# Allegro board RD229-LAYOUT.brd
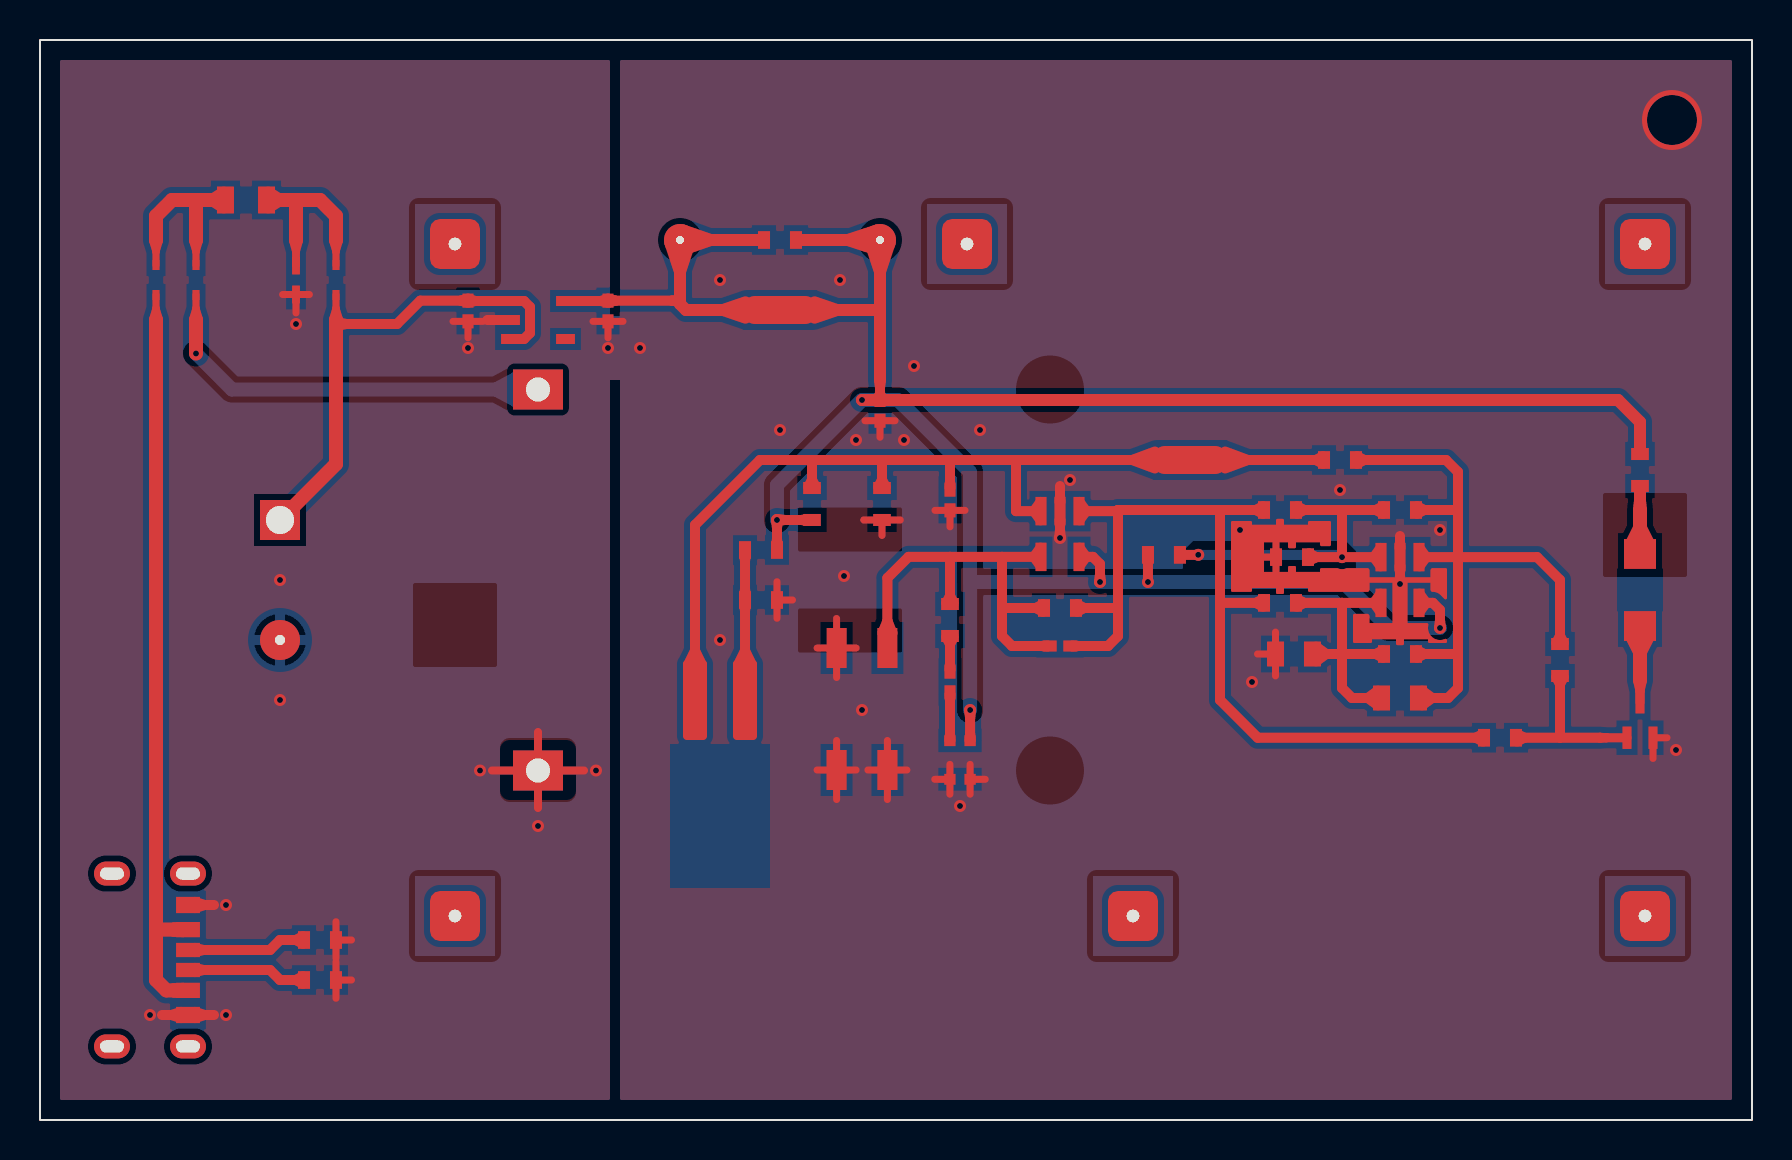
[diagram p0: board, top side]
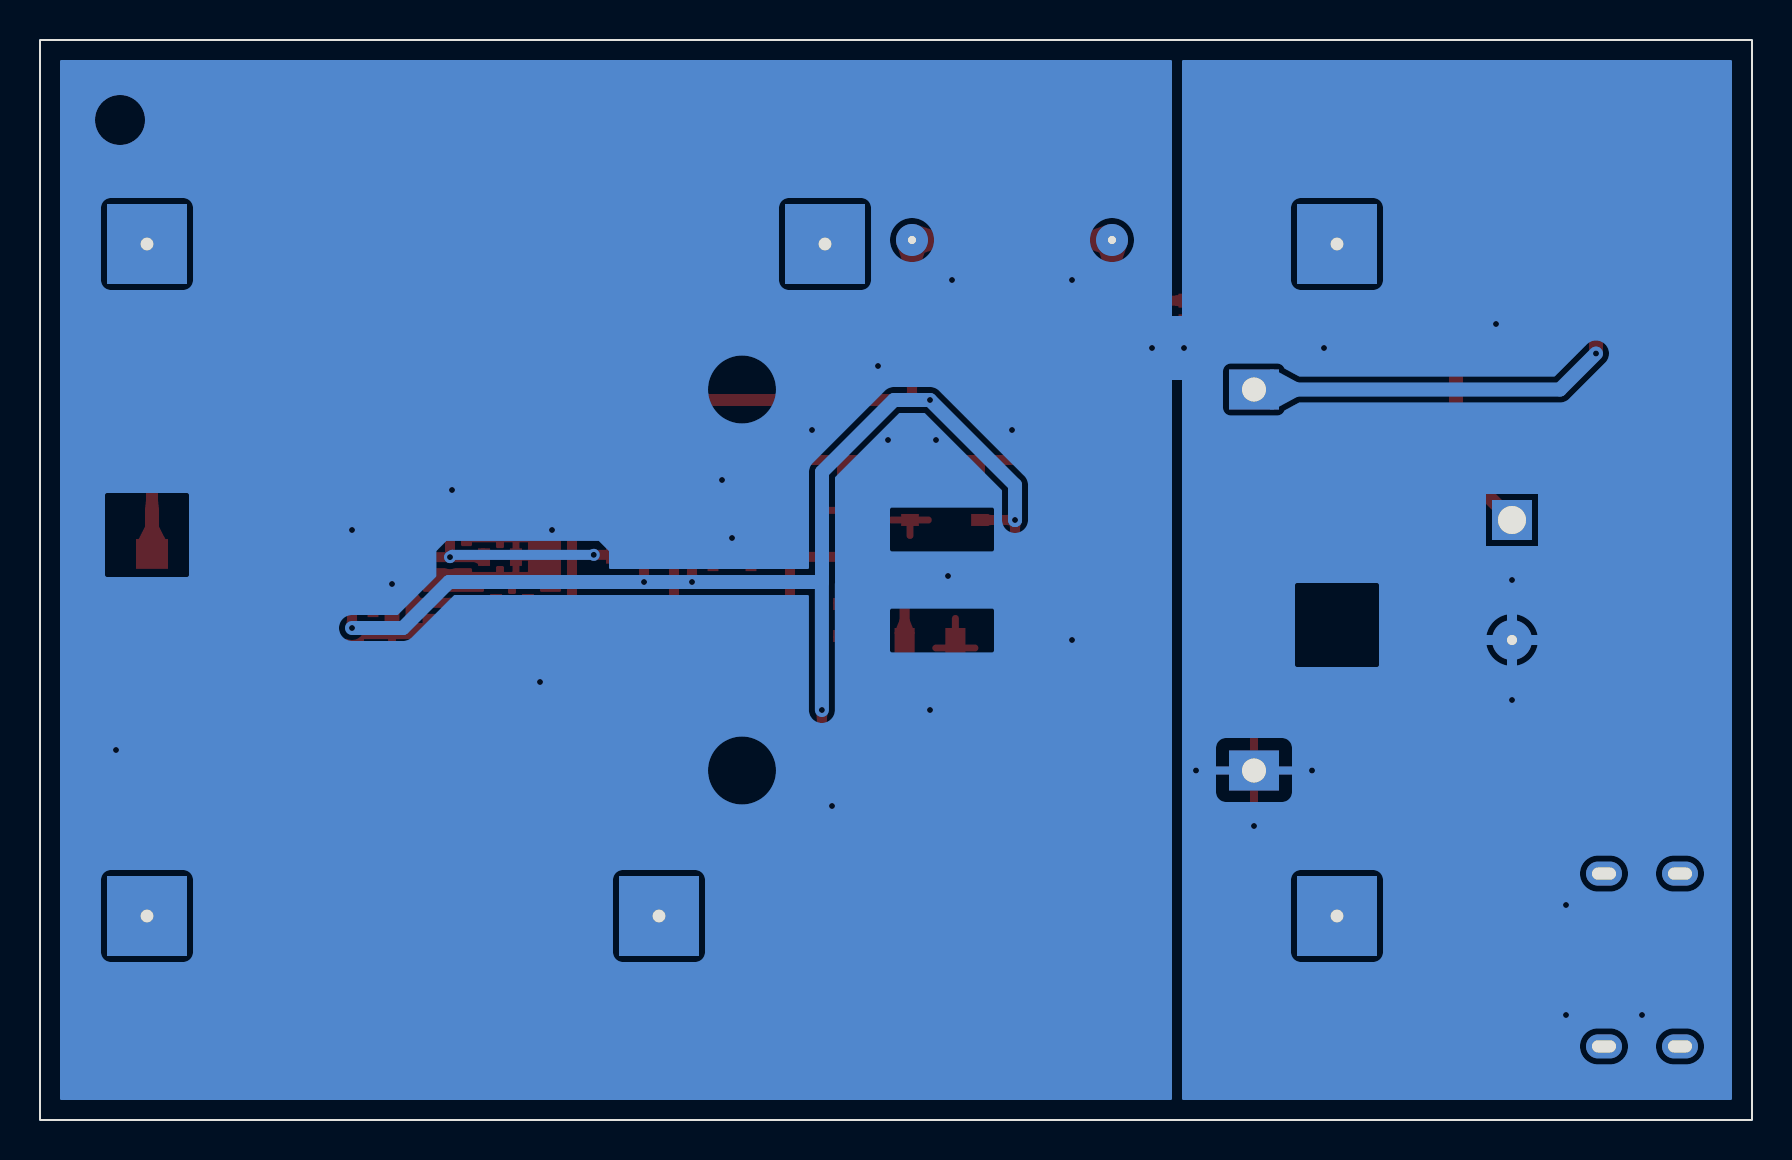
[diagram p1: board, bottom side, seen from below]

Outline 85.6 x 54 mm; copper layers: TOP, BOTTOM. Coordinates in mm from the lower left corner of the outline.
Outline path: rectangle 0,0 85.6,54

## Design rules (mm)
constraint set DEFAULT: 

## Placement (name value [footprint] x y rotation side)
C1  -  [CAP_GRM155B11A10]  21.4 40.45 90 top
C2  -  [CAP_GRM155B11A10]  28.4 40.45 90 top
C3  -  [CAP_GRM155B11A10]  42 35.48 90 top
C4  -  [CAP_GRM155B11A10]  45.5 21.9 270 top
C5  -  [CAP_GRM155B11A10]  45.5 31 90 top
C6  -  [CAP_GRM155B11A10]  51 23.7 0 top
C7  -  [G_21_MUR]  62.7 23.3 0 top
C8  -  [G_21_MUR]  68 21.1 0 top
CN1  -  [CONN6_125_GF_A_0]  5.5 8 270 top
D1  -  [ESC_TOS]  5.8 42 270 top
D2  -  [ESC_TOS]  7.8 42 270 top
D3  -  [SOD523_NEX]  12.8 42 270 top
D4  -  [ESC_TOS]  14.8 42 90 top
EDLC1  -  [CAP_EEC_F5R5U105]  12 27 0 top
JP1  -  [RES_TTD1002F_KOA_2]  37 44 0 top
JP2  -  [RES_TTD1002F_KOA_2]  36.05 28.5 0 top
JP3  -  [RES_TTD1002F_KOA_2]  36.05 26 0 top
JP4  -  [RES_TTD1002F_KOA_2]  73 19.11 0 top
JP5  -  [RES_TTD1002F_KOA_2]  76 23 270 top
LED1  -  [LED_LTST_C230KGK]  80 26.5 90 top
M1  -  [CMM2718AT42308TR]  46 18 0 top
OP1  -  [SOT_25__SMV_T]  51 29.3 270 top
OP2  -  [SOT_25__SMV_T]  68 27 270 top
PD1  -  [PD_4]  41.1 20.5 270 top
Q1  -  [USM_TOS]  80 20 0 top
R1  -  [RES_TTD1002F_KOA_2]  80 32.5 270 top
R2  -  [RES_TTD1002F_KOA_2]  45.5 25 270 top
R3  -  [RES_TTD1002F_KOA_2]  38.6 30.8 270 top
R4  -  [RES_TTD1002F_KOA_2]  42.1 30.8 90 top
R5  -  [RES_TTD1002F_KOA_2]  51 25.6 0 top
R6  -  [RES_TTD1002F_KOA_2]  62 30.5 0 top
R7  -  [RES_TTD1002F_KOA_2]  68 30.5 0 top
R8  -  [RES_TTD1002F_KOA_2]  62.6 28.14 0 top
R9  -  [RES_TTD1002F_KOA_2]  68 23.3 0 top
R10  -  [RES_TTD1002F_KOA_2]  62 25.86 0 top
R11  -  [RES_TTD1002F_KOA_2]  65 33 180 top
R12  -  [RES_TTD1002F_KOA_2]  14 9 180 top
R13  -  [RES_TTD1002F_KOA_2]  14 7 180 top
R14  -  [RES_RK73H2A_KOA]  10.3 46 180 top
R15  -  [RES_TTD1002F_KOA_2]  56.2 28.26 0 top
S1  -  [FSR400_S]  34 21 270 top
SJ1  -  [SJ_1_1]  37 40.5 0 top
SJ2  -  [SJ_1_1]  57.5 33 0 top
SM1  -  [SOLAR_CELL_2]  50.5 27 0 bottom
TP1  -  [T_PAD]  32 44 0 top
TP2  -  [T_PAD]  42 44 0 top
U1  -  [SMV_SOT_25_SC_7]  24.9 40 0 top

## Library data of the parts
C1-C6 = GRM155B11A104KA0: alternate symbols: (T:CAP_GRM155B11A10,CAP_GRM155B11A10_2,CAP_GRM155B11A10_3,CAP_GRM155B11A10_1,CAP_GRM155B11A10_4,CAP_GRM155B11A10_5;B:CAP_GRM155B11A10_B,CAP_GRM155B11A10_2_B,CAP_GRM155B11A10_3_B,CAP_GRM155B11A10_1_B,CAP_GRM155B11A10_4_B,CAP_GRM155B11A10_5_B)
C7 C8 = GRM21BR60J226ME3: alternate symbols: (T:G_21_MUR,G_21_MUR_1;B:G_21_MUR_B,G_21_MUR_1_B)
CN1 = USB4125-GF-A-019: alternate symbols: (T:CONN6_125_GF_A_0;B:CONN6_125_GF_A_0_B)
D1 D2 D4 = 1SS389_L3F_T: alternate symbols: (T:ESC_TOS,ESC_TOS_1,ESC_TOS_2;B:ESC_TOS_B,ESC_TOS_1_B,ESC_TOS_2_B)
D3 = PESD15VS1UB: alternate symbols: (T:SOD523_NEX;B:SOD523_NEX_B)
EDLC1 = EEC-F5R5U105: alternate symbols: (T:CAP_EEC_F5R5U105;B:CAP_EEC_F5R5U105_B)
JP1-JP5 R1-R13 R15 = RK73H1JTTD1002F: alternate symbols: (T:RES_TTD1002F_KOA_2,RES_TTD1002F_KOA_16,RES_TTD1002F_KOA_17,RES_TTD1002F_KOA_3,RES_TTD1002F_KOA_4,RES_TTD1002F_KOA_1,RES_TTD1002F_KOA_13,RES_TTD1002F_KOA,RES_TTD1002F_KOA_14,RES_TTD1002F_KOA_12,RES_TTD1002F_KOA_5,RES_TTD1002F_KOA_6,RES_TTD1002F_KOA_7,RES_TTD1002F_KOA_8,RES_TTD1002F_KOA_9,RES_TTD1002F_KOA_10,RES_TTD1002F_KOA_11,RES_TTD1002F_KOA_15;B:RES_TTD1002F_KOA_2_B,RES_TTD1002F_KOA_16_B,RES_TTD1002F_KOA_17_B,RES_TTD1002F_KOA_3_B,RES_TTD1002F_KOA_4_B,RES_TTD1002F_KOA_1_B,RES_TTD1002F_KOA_13_B,RES_TTD1002F_KOA_B,RES_TTD1002F_KOA_14_B,RES_TTD1002F_KOA_12_B,RES_TTD1002F_KOA_5_B,RES_TTD1002F_KOA_6_B,RES_TTD1002F_KOA_7_B,RES_TTD1002F_KOA_8_B,RES_TTD1002F_KOA_9_B,RES_TTD1002F_KOA_10_B,RES_TTD1002F_KOA_11_B,RES_TTD1002F_KOA_15_B)
LED1 = LTST-C230KGKT: alternate symbols: (T:LED_LTST_C230KGK;B:LED_LTST_C230KGK_B)
M1 = CMM-2718AT-42308-TR: alternate symbols: (T:CMM2718AT42308TR;B:CMM2718AT42308TR_B)
OP1 OP2 = TC75S102F_LF_CT: alternate symbols: (T:SOT_25__SMV_T,SOT_25__SMV_T_2;B:SOT_25__SMV_T_B,SOT_25__SMV_T_2_B)
PD1 = S7184: alternate symbols: (T:PD_4;B:PD_4_B)
Q1 = SSM3K15AFU_LF_T: alternate symbols: (T:USM_TOS;B:USM_TOS_B)
R14 = RK73H2ATTD1003F: alternate symbols: (T:RES_RK73H2A_KOA;B:RES_RK73H2A_KOA_B)
S1 = FSR400-S: alternate symbols: (T:FSR400_S;B:FSR400_S_B)
SJ1 SJ2 = SJ-1: alternate symbols: (T:SJ_1_1;B:SJ_1_1_B)
SM1 = LR0GC02: alternate symbols: (T:solar_cell_2;B:solar_cell_2_B)
TP1 TP2 = T-PAD1: alternate symbols: (T:T_PAD;B:T_PAD_B)
U1 = TCR3UF20A_LM_CT: alternate symbols: (T:SMV_SOT_25_SC_7;B:SMV_SOT_25_SC_7_B)

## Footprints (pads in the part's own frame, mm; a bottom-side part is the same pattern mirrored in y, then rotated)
CAP_EEC_F5R5U105
  rect 2x2 hole 1.4: 1(0,3)
  custom 0.5x0.5 hole 1.4: 2(0,-3)
CAP_GRM155B11A10
  custom 0.138x0.138 smd: 1(-0.518,0) 2(0.518,0)
CMM2718AT42308TR
  custom 0.135x0.135 smd: 1(0.505,0.965) 2(0.505,-0.965) 3(-0.505,-0.965) 4(-0.505,0.965)
CONN6_125_GF_A_0
  custom 0.203x0.203 smd: 1(-2.75,1.9) 6(2.75,1.9)
  custom 0.19x0.19 smd: 2(-1.52,1.9) 5(1.52,1.9)
  custom 0.177x0.177 smd: 3(-0.5,1.9) 4(0.5,1.9)
  oval 1.2x1.8 hole 0.6x1.2: 7(-4.32,1.9) 8(-4.32,-1.9) 9(4.32,1.9) 10(4.32,-1.9)
ESC_TOS
  custom 0.087x0.087 smd: 1(-0.75,0) 2(0.75,0)
FSR400_S
  custom 0.3x0.3 smd: 1(0,1.25) 2(0,-1.25)
G_21_MUR
  custom 0.212x0.212 smd: 1(-0.924,0) 2(0.924,0)
LED_LTST_C230KGK
  custom 0.372x0.372 smd: 1(-1.803,0) 2(1.803,0)
PD_4
  custom 0.25x0.25 smd: 1(-3.1,1.27) 2(-3.1,-1.27) 3(3,-1.27) 4(3,1.27)
RES_RK73H2A_KOA
  custom 0.212x0.212 smd: 1(-1.026,0) 2(1.026,0)
RES_TTD1002F_KOA_2
  custom 0.15x0.15 smd: 1(-0.799,0) 2(0.799,0)
SJ_1_1
  custom 0.35x0.35 smd: 1(-0.9,0) 2(0.9,0)
SMV_SOT_25_SC_7
  custom 0.125x0.125 smd: 1(-1.375,0.95) 2(-1.375,0) 3(-1.375,-0.95) 4(1.375,-0.95) 5(1.375,0.95)
SOD523_NEX
  custom 0.098x0.098 smd: 1(-0.725,0) 2(0.725,0)
SOLAR_CELL_2
  rect 2.5x2 hole 1.2: 1(-25.6,-9.525) 4(-25.6,9.525)
  custom 0.625x0.625 hole 1.2: 7(-4.15,-16.8) 8(29.75,-16.8) 10(29.75,16.8) 11(4.15,16.8) 12(-29.75,16.8) 14(-29.75,-16.8)
SOT_25__SMV_T
  custom 0.138x0.138 smd: 1(-1.144,0.95) 2(-1.144,0) 3(-1.144,-0.95) 4(1.144,-0.95) 5(1.144,0.95)
T_PAD
  custom 0.4x0.4 hole 1: 1(0,0)
USM_TOS
  custom 0.113x0.113 smd: 1(-0.65,-0.887) 2(0.65,-0.887) 3(0,0.887)

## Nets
GND: C1.1 C2.1 C3.1 C5.1 C7.1 CN1.1 CN1.6 D3.2 EDLC1.2 JP3.2 M1.2 M1.3 OP1.2 OP2.2 PD1.2 PD1.3 PD1.4 Q1.2 R4.1 R8.1 R12.1 R13.1 SM1.4 U1.2
VDD(2V): C3.2 JP1.2 JP2.2 M1.1 OP1.5 OP2.5 R1.1 R3.2 R15.1 SJ1.2 TP2.1
N00100001: JP4.2 JP5.2 Q1.1
N00100002: D2.2 SM1.1
N00100008: LED1.2 R1.2
N00100010: LED1.1 Q1.3
N00100012: C8.2 JP5.1 OP2.1 R7.2 R9.2 R11.1
N00100013: C2.2 JP1.1 SJ1.1 TP1.1 U1.5
N00100014: OP2.3 R6.2 R7.1 R8.2 R15.2
N00100018: C6.2 JP4.1 OP1.1 R5.2 R6.1 R10.1
N00100019: C1.2 D4.1 EDLC1.1 U1.1 U1.3
N00100021: D3.1 D4.2 R14.1
N00100022: C7.2 C8.1 OP2.4 R9.1 R10.2
N00100023: C4.1 R2.2
N00100024: CN1.2 CN1.5 D1.2
N00100025: CN1.3 R12.2
N00100026: CN1.4 R13.2
N00100027: C5.2 OP1.3 R3.1 R4.2 S1.2 SJ2.1
N00100030: JP2.1 JP3.1 S1.1
N00100031: D1.1 D2.1 R14.2
N00100032: C4.2 M1.4
N00100039: C6.1 OP1.4 PD1.1 R2.1 R5.1
N00100047: R11.2 SJ2.2

Pads without a net: CN1 7 8 9 10; SM1 7 8 10 11 12 14; U1 4

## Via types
v1: diameter 0.6, hole 0.3, TOP to BOTTOM, 40 vias
v2: diameter 3, hole 2.5, TOP to BOTTOM, 1 via

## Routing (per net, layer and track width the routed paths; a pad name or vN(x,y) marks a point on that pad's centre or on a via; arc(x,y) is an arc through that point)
GND: length 85
  TOP w0.35: M1.3 44.74,17.04 ; M1.3 45.49,17.78 ; M1.3 45.49,16.29 ; PD1.4 42.37,16.02 ; PD1.4 41.4,17.5 ; PD1.4 43.34,17.5 ; PD1.4 42.37,18.98 ; JP3.2 37.62,26 ; JP3.2 36.85,26.91 ; JP3.2 36.85,25.09 ; C3.1 42,34.14 ; C3.1 42.75,34.96 ; C3.1 41.25,34.96 ; M1.2 46.51,17.78 ; M1.2 46.51,16.29 ; M1.2 47.26,17.04 ; R8.1 61.8,27.23 ; R8.1 61.03,28.14 ; R8.1 61.8,29.06 ; R12.1 14.8,8.09 ; R12.1 14.8,9.91 ; R12.1 15.57,9 ; R4.1 41.19,30 ; R4.1 42.1,29.23 ; R4.1 43.02,30 ; D3.2 12.8,40.35 ; D3.2 13.47,41.27 ; D3.2 12.13,41.27 ; C1.1 22.15,39.93 ; C1.1 21.4,39.11 ; C1.1 20.65,39.93 ; PD1.3 39.83,16.02 ; PD1.3 40.8,17.5 ; PD1.3 39.83,18.98 ; PD1.3 38.85,17.5 ; R13.1 14.8,7.92 ; R13.1 14.8,6.08 ; R13.1 15.57,7 ; C5.1 45.5,29.66 ; C5.1 44.75,30.48 ; C5.1 46.25,30.48 ; PD1.2 39.83,25.07 ; PD1.2 38.85,23.6 ; PD1.2 40.8,23.6 ; PD1.2 39.83,22.12 ; C2.1 28.4,39.11 ; C2.1 27.65,39.93 ; C2.1 29.15,39.93 ; C7.1 61.78,24.39 ; C7.1 61.78,22.2 ; C7.1 60.88,23.3 ; 81.35,19.11 Q1.2 80.65,18.08
  TOP w0.4: SM1.4 24.9,19.4 ; SM1.4 27.2,17.48 ; SM1.4 22.6,17.48 ; SM1.4 24.9,15.6
  TOP w0.5: 67.97,27.68 68,27.35 ; 68,27.35 68,27.21 ; 68,27.35 68.03,27.68 ; 68,27.35 OP2.2 68,28.93 ; 8.23,5.25 CN1.6 6.57,5.25 ; 8.23,5.25 7.75,5.41 ; 8.23,5.25 7.75,5.09 ; 8.23,5.25 8.7,5.25 ; 7.75,10.9 8.23,10.75 ; 8.23,10.75 CN1.1 ; 8.23,10.75 8.7,10.75 ; 8.23,10.75 7.75,10.6 ; 68,27.21 68.05,26.81 ; 68,27.21 67.95,26.81 ; 68,27.21 v1(68,26.8) ; U1.2 22.37,40 ; 51,31.23 OP1.2 51,29.65 ; 51,31.23 51.02,30.9 ; 51,31.23 51,31.7 ; 51,31.23 50.98,30.9 ; 51,29.65 51.02,29.98 ; 51,29.65 51,29.51 ; 51,29.65 50.98,29.98 ; 51.05,29.11 51,29.51 ; 51,29.51 50.95,29.11 ; 51,29.51 v1(51,29.1) ; 68,28.93 68,29.2 ; 68,28.93 67.97,28.6 ; 68,28.93 68.03,28.6 ; 7.05,5.09 6.57,5.25 ; 6.57,5.25 6.1,5.25 ; 6.57,5.25 7.05,5.41
  BOTTOM w0.4: 22.7,17.48 SM1.4 27.1,17.48
  BOTTOM w0.5: EDLC1.2 10.45,24 ; EDLC1.2 12,25.55 ; EDLC1.2 12,22.45 ; EDLC1.2 13.55,24
  vias: v1(5.5,5.25) v1(9.3,10.75) v1(9.3,5.25) v1(12,27) v1(12,21) v1(12.8,39.8) v1(21.4,38.6) v1(22,17.48) v1(24.9,14.7) v1(27.8,17.48) v1(28.4,38.6) v1(30,38.6) v1(34,42) v1(34,24) v1(37,34.5) v1(40,42) v1(40.2,27.2) v1(40.8,34) v1(41.1,20.5) v1(43.2,34) v1(43.7,37.7) v1(46,15.7) v1(47,34.5) v1(51.5,32) v1(60,29.5) v1(60.6,21.9) v1(65,31.5) v1(70,29.5) v1(81.8,18.5) v2(81.6,50)
VDD(2V): length 133.4
  TOP w0.5: 53.05,26.91 53,27.31 ; 53,27.31 v1(53,26.9) ; 53,27.31 53,27.8 52.64,28.16 52.3,28.16 ; 53,27.31 52.95,26.91 ; 68.97,25.65 69.31,25.86 ; 69.31,25.86 69.64,25.86 70,25.5 70,25.01 ; 69.31,25.86 68.97,26.32 ; 69.31,25.86 68.97,25.4 ; 69.31,25.86 68.97,25.9 ; 69.31,25.86 OP2.5 ; 46.51,20.09 46.51,19.31 ; 46.51,20.09 v1(46.51,20.5) ; 46.51,20.09 46.46,20.49 ; 46.51,20.09 46.55,20.49 ; 46.51,19.31 46.48,18.98 ; 46.51,19.31 M1.1 ; 46.51,19.31 46.53,18.98 ; 51.98,28.62 52.3,28.16 ; 52.3,28.16 51.98,27.95 ; 52.3,28.16 51.98,27.7 ; 52.3,28.16 51.98,28.2 ; 52.3,28.16 OP1.5 ; 37.26,30 38.05,30 ; 37.26,30 36.86,30.05 ; 37.26,30 36.86,29.95 ; 37.26,30 v1(36.85,30) 36.85,29.59 ; 38.05,30 38.41,30.05 ; 38.05,30 38.41,29.95 ; 38.05,30 R3.2 ; 70,25.01 v1(70,24.6) ; 70,25.01 70.05,24.61 ; 70,25.01 69.95,24.61 ; 36.85,29.59 36.9,29.99 ; 36.85,29.59 36.85,29.05 ; 36.85,29.59 36.8,29.99 ; 42,36.43 C3.2 ; 42,36.43 42,36.59 ; 42,36.43 41.98,36.1 ; 42,36.43 42.02,36.1 ; 42,36.59 42.05,36.99 ; 42,36.59 41.95,36.99 ; 42,36.59 42,37 ; 36.9,28.69 36.85,29.05 ; 36.85,29.05 36.8,28.69 ; 36.85,29.05 JP2.2 ; R15.1 v1(55.4,26.9)
  TOP w0.6: 38.73,40.88 39.84,40.5 ; 39.84,40.5 38.73,40.42 ; 39.84,40.5 SJ1.2 ; 39.84,40.5 38.73,40.12 ; 39.84,40.5 42,40.5 ; 42,37 42,40.5 ; 42,40.5 TP2.1 JP1.2 ; R1.1 80,34.9 78.9,36 C3.2 v1(41.1,36)
  BOTTOM w0.7: v1(36.85,30) 36.85,31.75 v1(41.1,36) 42.9,36 46.5,32.4 46.5,26.9 ; v1(70,24.6) 67.45,24.6 65.15,26.9 v1(55.4,26.9) v1(53,26.9) 46.5,26.9 ; 46.5,26.9 46.51,26.89 v1(46.51,20.5)
N00100001: length 10.9
  TOP w0.45: 78,19.09 78.33,19.11 ; 78.33,19.11 Q1.1 ; 78.33,19.11 78,19.11 ; 78.33,19.11 78,19.14
  TOP w0.5: 73.85,18.92 74.21,19.11 ; 74.21,19.11 73.85,19.3 ; 74.21,19.11 JP4.2 ; 74.21,19.11 76,19.11 ; 76,19.11 78,19.11 ; 76,19.11 76,21.79 ; 76,21.79 76.19,22.15 ; 76,21.79 JP5.2 ; 76,21.79 75.81,22.15
N00100002: length 27.1
  TOP w0.35: 7.8,40.59 7.63,40.05 ; 7.8,40.59 7.8,40 ; 7.8,40.59 7.97,40.05 ; 7.8,40.59 D2.2
  TOP w0.7: v1(7.8,38.33) 7.8,40
  BOTTOM w0.7: 24,35.88 22.8,36.52 ; 22.8,36.52 24,36.23 ; 22.8,36.52 24,37.17 ; 22.8,36.52 24,36.58 ; 22.8,36.52 9.6,36.52 v1(7.8,38.33) ; 22.8,36.52 SM1.1
N00100008: length 7.2
  TOP w0.6: 80,30.97 79.95,30.51 ; 80,30.97 R1.2 ; 80,30.97 80.05,30.51 ; 80,30.97 80,30.5
  TOP w0.7: 80.45,28.7 80,29.59 ; 80,29.59 80,30.5 ; 80,29.59 79.55,28.7 ; 80,29.59 80.1,28.7 ; 80,29.59 LED1.2
N00100010: length 7.8
  TOP w0.45: Q1.3 80,21.45 ; 80,21.45 80,22 ; 80,21.45 80.12,21.97 ; 80,21.45 79.88,21.97
  TOP w0.7: 80,23.41 LED1.1 ; 80,23.41 80.45,24.3 ; 80,23.41 79.55,24.3 ; 80,23.41 79.9,24.3 ; 80,23.41 80,22
N00100012: length 40.2
  TOP w0.5: 69.21,30.5 70.9,30.5 ; 69.21,30.5 68.85,30.31 ; 69.21,30.5 R7.2 ; 69.21,30.5 68.85,30.69 ; 70.9,30.5 70.9,32.4 70.3,33 66.21,33 ; 70.9,30.5 70.9,28.14 ; 69.31,28.14 70.9,28.14 ; 69.31,28.14 OP2.1 ; 69.31,28.14 68.97,28.6 ; 69.31,28.14 68.97,28.18 ; 69.31,28.14 68.97,27.93 ; 69.31,28.14 68.97,27.68 ; 70.9,28.14 70.9,23.3 ; 70.9,28.14 74.86,28.14 76,27 76,24.21 ; 66.21,33 65.85,33.19 ; 66.21,33 65.85,32.81 ; 66.21,33 R11.1 ; 76.19,23.85 76,24.21 ; 76,24.21 75.81,23.85 ; 76,24.21 JP5.1 ; 69.61,21.1 70.4,21.1 70.9,21.6 70.9,23.3 ; 69.61,21.1 69.1,21.47 ; 69.61,21.1 C8.2 ; 69.61,21.1 69.1,20.73 ; 69.61,21.1 69.1,20.98 ; 70.9,23.3 69.21,23.3 ; 69.21,23.3 R9.2 ; 69.21,23.3 68.85,23.49 ; 69.21,23.3 68.85,23.11
N00100013: length 21.1
  TOP w0.5: 31.59,40.97 31.99,40.92 ; 31.59,40.97 31.99,41.02 ; 31.59,40.97 28.75,40.97 ; 31.59,40.97 32,40.97 ; 28.38,41.07 28.05,40.95 ; 28.05,40.95 U1.5 ; 28.05,40.95 28.38,40.95 C2.2 28.75,40.97 ; 28.05,40.95 28.38,40.87 ; 28.75,40.97 28.43,40.87 ; 28.75,40.97 28.43,41.07
  TOP w0.6: JP1.1 TP1.1 32,40.8 32.3,40.5 34.16,40.5 ; 35.27,40.58 34.16,40.5 ; 34.16,40.5 35.27,40.12 ; 34.16,40.5 35.27,40.88
N00100014: length 22.9
  TOP w0.5: 63.45,28.33 63.81,28.14 ; 63.81,28.14 R8.2 ; 63.81,28.14 v1(65.1,28.14) ; 63.81,28.14 63.45,27.95 ; 67.03,28.1 66.69,28.14 ; 66.69,28.14 67.03,28.6 ; 66.69,28.14 67.03,27.68 ; 66.69,28.14 v1(65.1,28.14) ; 66.69,28.14 OP2.3 ; 66.69,28.14 67.03,28.35 ; 62.85,30.31 63.21,30.5 ; 63.21,30.5 R6.2 ; 63.21,30.5 62.85,30.69 ; 63.21,30.5 65.1,30.5 ; 66.79,30.5 65.1,30.5 ; 66.79,30.5 67.15,30.31 ; 66.79,30.5 67.15,30.69 ; 66.79,30.5 R7.1 ; 65.1,30.5 v1(65.1,28.14) ; R15.2 v1(57.91,28.26)
  BOTTOM w0.5: v1(57.91,28.26) 64.99,28.26 v1(65.1,28.14)
N00100018: length 51.7
  TOP w0.5: 60.79,25.86 61.15,25.67 ; 60.79,25.86 61.15,26.05 ; 60.79,25.86 59,25.86 ; 60.79,25.86 R10.1 ; 72.15,19.3 71.79,19.11 ; 71.79,19.11 JP4.1 ; 71.79,19.11 60.89,19.11 59,21 59,25.86 ; 71.79,19.11 72.15,18.92 ; 51.98,30.23 52.3,30.44 ; 52.3,30.44 51.98,29.98 ; 52.3,30.44 OP1.1 ; 52.3,30.44 51.98,30.48 ; 52.3,30.44 51.98,30.9 ; 52.3,30.44 53.84,30.44 53.9,30.5 ; 53.9,30.5 53.9,25.6 ; 53.9,30.5 59,30.5 ; 53.9,25.6 53.9,24.2 53.4,23.7 51.95,23.7 ; 53.9,25.6 52.21,25.6 ; 52.21,25.6 51.85,25.41 ; 52.21,25.6 R5.2 ; 52.21,25.6 51.85,25.79 ; 61.15,30.69 60.79,30.5 ; 60.79,30.5 61.15,30.31 ; 60.79,30.5 R6.1 ; 60.79,30.5 59,30.5 ; 51.95,23.7 C6.2 ; 51.95,23.7 51.62,23.68 ; 51.95,23.7 51.62,23.73 ; 59,30.5 59,25.86
N00100019: length 28.7
  TOP w0.35: 14.8,40.59 D4.1 ; 14.8,40.59 14.63,40.05 ; 14.8,40.59 14.97,40.05 ; 14.8,40.59 14.8,40
  TOP w0.5: 14.82,39.7 15.32,39.8 ; 15.32,39.8 17.85,39.8 19.02,40.97 21.05,40.97 ; 15.32,39.8 14.82,39.9 ; 15.32,39.8 14.8,39.8 ; U1.3 24.2,39.05 24.5,39.35 24.5,40.65 24.2,40.95 U1.1 21.75,40.95 ; 21.05,40.97 21.38,40.87 ; 21.05,40.97 C1.2 21.42,40.95 21.75,40.95 ; 21.05,40.97 21.38,41.07 ; 21.75,40.95 21.43,41.07 ; 21.75,40.95 21.43,40.87
  TOP w0.7: 14.8,40 14.8,32.8 EDLC1.1
N00100021: length 13
  TOP w0.35: 14.63,43.95 14.8,43.41 ; 14.8,43.41 14.97,43.95 ; 14.8,43.41 14.8,44 ; 14.8,43.41 D4.2
  TOP w0.39: 12.65,43.96 12.8,43.42 ; 12.8,43.42 12.95,43.96 ; 12.8,43.42 12.8,44 ; 12.8,43.42 D3.1
  TOP w0.7: 14.8,44 14.8,45.2 14,46 12.8,46 ; 11.91,46 11.4,46.32 ; 11.91,46 12.8,46 ; 11.91,46 11.4,45.68 ; 11.91,46 R14.1 ; 12.8,46 12.8,44
N00100022: length 21.3
  TOP w0.5: 63.21,25.86 62.85,26.05 ; 63.21,25.86 62.85,25.67 ; 63.21,25.86 R10.2 ; 63.21,25.86 65.1,25.86 ; 67.03,25.4 66.69,25.86 ; 66.69,25.86 67.03,25.82 ; 66.69,25.86 OP2.4 ; 66.69,25.86 67.03,26.07 ; 66.69,25.86 67.03,26.32 ; 66.69,25.86 65.1,25.86 ; 65.1,23.3 65.1,21.6 65.6,21.1 66.39,21.1 ; 65.1,23.3 64.31,23.3 ; 65.1,23.3 66.79,23.3 ; 65.1,23.3 65.1,25.86 ; 63.8,23.67 64.31,23.3 ; 64.31,23.3 C7.2 ; 64.31,23.3 63.8,23.18 ; 64.31,23.3 63.8,22.93 ; 66.39,21.1 66.9,20.73 ; 66.39,21.1 66.9,21.47 ; 66.39,21.1 C8.1 ; 66.39,21.1 66.9,21.22 ; 67.15,23.49 66.79,23.3 ; 66.79,23.3 R9.1 ; 66.79,23.3 67.15,23.11
N00100023: length 3.3
  TOP w0.5: 45.52,22.52 45.5,22.85 ; 45.5,22.85 45.5,23.79 ; 45.5,22.85 C4.1 ; 45.5,22.85 45.48,22.52 ; R2.2 45.5,23.79 ; 45.5,23.79 45.31,24.15 ; 45.5,23.79 45.69,24.15
N00100024: length 40.6
  TOP w0.35: D1.2 5.8,40.59 ; 5.8,40.59 5.63,40.05 ; 5.8,40.59 5.8,40 ; 5.8,40.59 5.97,40.05
  TOP w0.7: 6.7,6.48 7.16,6.45 ; 6.7,6.48 CN1.5 ; 6.7,6.48 6.32,6.48 5.8,7 5.8,9.52 ; 6.7,6.48 7.16,6.51 ; 6.7,9.52 7.16,9.49 ; 6.7,9.52 5.8,9.52 ; 6.7,9.52 CN1.2 ; 6.7,9.52 7.16,9.55 ; 5.8,9.52 5.8,40
N00100025: length 7.7
  TOP w0.5: 12.79,9 R12.2 ; 12.79,9 12,9 11.5,8.5 8.17,8.5 ; 12.79,9 13.15,9.19 ; 12.79,9 13.15,8.81 ; 8.17,8.5 7.75,8.39 ; 8.17,8.5 CN1.3 ; 8.17,8.5 7.75,8.61
N00100026: length 7.7
  TOP w0.5: 7.75,7.39 8.17,7.5 ; 8.17,7.5 11.5,7.5 12,7 12.79,7 ; 8.17,7.5 7.75,7.61 ; 8.17,7.5 CN1.4 ; 12.79,7 13.15,6.81 ; 12.79,7 13.15,7.19 ; 12.79,7 R13.2
N00100027: length 53.2
  TOP w0.5: 38.79,31.65 38.6,32.01 ; 38.6,32.01 38.6,33 ; 38.6,32.01 R3.1 ; 38.6,32.01 38.41,31.65 ; R4.2 42.1,32.01 ; 42.1,32.01 42.1,33 ; 42.1,32.01 42.29,31.65 ; 42.1,32.01 41.91,31.65 ; 32.75,23.47 32.75,29.75 36,33 38.6,33 ; 32.75,23.47 S1.2 ; 32.75,23.47 32.85,22.75 ; 32.75,23.47 32.4,22.75 ; 32.75,23.47 33.1,22.75 ; 38.6,33 42.1,33 ; 50.02,30.9 49.7,30.44 ; 49.7,30.44 50.02,30.4 ; 49.7,30.44 48.8,30.44 48.8,33 ; 49.7,30.44 50.02,29.98 ; 49.7,30.44 50.02,30.65 ; 49.7,30.44 OP1.3 ; 54.61,33 SJ2.1 ; 54.61,33 55.74,32.92 ; 54.61,33 55.74,32.58 ; 54.61,33 55.74,33.42 ; 54.61,33 55.74,33.17 ; 54.61,33 48.8,33 ; 42.1,33 45.5,33 ; 45.5,33 48.8,33 ; 45.5,33 45.5,31.95 ; 45.52,31.62 45.5,31.95 ; 45.5,31.95 C5.2 ; 45.5,31.95 45.48,31.62
N00100030: length 12
  TOP w0.5: 35.25,27.95 35.3,28.31 ; 35.25,27.95 35.2,28.31 ; 35.25,27.95 JP2.1 ; 35.25,27.95 35.25,26.55 ; 34.9,22.75 35.25,23.47 ; 35.25,23.47 35.25,21 S1.1 ; 35.25,23.47 35.35,22.75 ; 35.25,23.47 35.25,25.45 ; 35.25,23.47 35.6,22.75 ; 35.25,25.45 35.3,25.81 ; 35.25,25.45 35.2,25.81 ; 35.25,25.45 JP3.1 35.25,26.55 ; 35.25,26.55 35.2,26.19 ; 35.25,26.55 35.3,26.19
N00100031: length 13
  TOP w0.35: 7.8,44 7.8,43.41 ; 7.8,43.41 7.97,43.95 ; 7.8,43.41 7.63,43.95 ; 7.8,43.41 D2.1 ; 5.8,43.41 D1.1 ; 5.8,43.41 5.97,43.95 ; 5.8,43.41 5.8,44 ; 5.8,43.41 5.63,43.95
  TOP w0.7: 9.2,46.32 8.69,46 ; 8.69,46 7.8,46 ; 8.69,46 R14.2 ; 8.69,46 9.2,45.68 ; 7.8,46 7.8,44 ; 7.8,46 6.6,46 5.8,45.2 5.8,44
N00100032: length 3.7
  TOP w0.5: C4.2 45.5,20.95 ; 45.5,20.95 45.52,21.28 ; 45.5,20.95 45.48,21.28 ; 45.5,20.95 45.5,19.31 ; 45.5,19.31 45.47,18.98 ; 45.5,19.31 45.52,18.98 ; 45.5,19.31 45.5,18.97 M1.4
N00100039: length 28.1
  TOP w0.5: 42.37,24.95 42.37,27.1 43.43,28.16 45.5,28.16 ; 42.37,24.95 42.62,24.35 ; 42.37,24.95 PD1.1 ; 42.37,24.95 42.12,24.35 ; 50.05,23.7 C6.1 ; 50.05,23.7 50.38,23.73 ; 50.05,23.7 50.38,23.68 ; 50.05,23.7 48.6,23.7 48.1,24.2 48.1,25.6 ; 50.02,27.7 49.7,28.16 ; 49.7,28.16 48.1,28.16 ; 49.7,28.16 50.02,28.62 ; 49.7,28.16 OP1.4 ; 49.7,28.16 50.02,28.12 ; 49.7,28.16 50.02,28.37 ; 45.5,28.16 45.5,26.21 ; 45.5,28.16 48.1,28.16 ; 45.31,25.85 45.5,26.21 ; 45.5,26.21 45.69,25.85 ; 45.5,26.21 R2.1 ; 48.1,28.16 48.1,25.6 ; 49.79,25.6 R5.1 ; 49.79,25.6 48.1,25.6 ; 49.79,25.6 50.15,25.79 ; 49.79,25.6 50.15,25.41
N00100047: length 11.3
  TOP w0.5: 60.39,33 59.26,33.42 ; 60.39,33 59.26,33.08 ; 60.39,33 59.26,32.83 ; 60.39,33 59.26,32.58 ; 60.39,33 63.79,33 ; 60.39,33 SJ2.2 ; 63.79,33 64.15,32.81 ; 63.79,33 R11.2 ; 63.79,33 64.15,33.19

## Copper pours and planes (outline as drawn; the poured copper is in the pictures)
GND on TOP (solid shape): outline of 177 points within 59.55,23.74 70.35,30.06
GND on BOTTOM (solid shape): outline of 975 points within 1,1 84.6,53
GND on TOP: 65.7,28.69 65.65,28.74 65.65,29.9 65.7,29.95 66.55,29.95 66.6,29.9 66.6,29.76 67.11,29.76 67.8,29.76 67.8,30.01 67.85,30.06 68.15,30.06 68.2,30.01 68.2,29.76 68.89,29.76 69.4,29.76 69.4,29.9 69.45,29.95 70.3,29.95 70.35,29.9 70.35,28.74 70.3,28.69 69.61,28.69 69.53,28.8 69.53,29.15 69,29.15 68.95,29.15 67.05,29.15 67,29.15 66.47,29.15 66.47,28.8 66.39,28.69
GND on TOP: outline of 177 points within 59.55,23.74 70.35,30.06
GND on TOP: 33.58,18.8 33.65,19.2 33.65,22.75 33.52,23.14 33.3,23.59 33.3,23.61 33.3,29.5 33.31,29.54 36.21,32.44 36.25,32.45 38,32.45 38.05,32.4 38.05,32.25 38,32.2 37.86,32.2 37.86,31.69 37.86,31 38.11,31 38.16,30.95 38.16,30.65 38.11,30.6 37.86,30.6 37.81,30.55 37.3,30.55 37.29,30.55 36.87,30.6 36.72,30.59 36.67,30.57 36.62,30.56 36.57,30.53 36.53,30.51 36.48,30.48 36.44,30.44 36.41,30.41 36.37,30.37 36.34,30.32 36.32,30.28 36.29,30.23 36.28,30.18 36.26,30.13 36.25,29.98 36.3,29.56 36.3,29.55 36.3,29.29 36.25,29.24 36.25,28.99 36.2,28.94 35.9,28.94 35.85,28.99 35.85,29.24 34.65,29.24 34.65,28.32 34.65,28.27 34.65,27.76 34.7,27.71 34.7,26.79 34.65,26.74 34.65,26.23 34.65,26.18 34.65,25.82 34.65,25.77 34.65,25.26 34.7,25.21 34.7,23.61 34.7,23.59 34.48,23.14 34.35,22.75 34.35,19.2 34.42,18.8
GND on TOP: 61.85,30.94 61.8,30.99 61.8,31.24 61.11,31.24 60.6,31.24 60.6,31.1 60.55,31.05 53.93,31.05 53.64,30.99 52.61,30.99 52.52,31.1 52.52,31.45 51.95,31.45 50.05,31.45 49.48,31.45 49.48,31.1 49.35,31.06 49.35,32.4 49.4,32.45 54.5,32.45 54.52,32.45 55.51,32.08 55.57,32.05 55.65,32 55.91,32 59.11,32 59.19,32 59.27,32.01 59.36,32.03 59.44,32.06 60.48,32.45 60.5,32.45 63.55,32.45 63.6,32.4 63.6,32.26 64.11,32.26 64.8,32.26 64.8,32.51 64.85,32.56 65.15,32.56 65.2,32.51 65.2,32.26 65.89,32.26 66.4,32.26 66.4,32.4 66.45,32.45 70.05,32.45 70.09,32.44 70.34,32.19 70.35,32.15 70.35,31.1 70.3,31.05 69.45,31.05 69.4,31.1 69.4,31.24 68.89,31.24 68.2,31.24 68.2,30.99 68.15,30.94 67.85,30.94 67.8,30.99 67.8,31.24 67.11,31.24 66.6,31.24 66.6,31.1 66.55,31.05 63.45,31.05 63.4,31.1 63.4,31.24 62.89,31.24 62.2,31.24 62.2,30.99 62.15,30.94
GND on TOP: outline of 110 points within 59.55,19.56 75.56,27.59
GND on TOP: 32.65,41.1 32.6,41.15 32.6,42.43 32.6,42.44 32.85,43.12 32.88,43.15 33.56,43.4 33.57,43.4 35.55,43.4 35.6,43.26 36.8,43.26 36.8,43.51 36.85,43.56 37.15,43.56 37.2,43.51 37.2,43.26 38.4,43.26 38.45,43.4 40.43,43.4 40.44,43.4 41.12,43.15 41.15,43.12 41.4,42.44 41.4,42.43 41.4,41.15 41.35,41.1 39.95,41.1 39.93,41.1 38.94,41.44 38.85,41.5 38.59,41.5 35.45,41.5 35.38,41.5 35.3,41.5 35.21,41.48 35.13,41.46 35.03,41.43 34.07,41.1 34.05,41.1
GND on TOP: outline of 753 points within 1,1 84.6,53 ; 17 cut-outs
GND on BOTTOM: 29,40.2 29,52.93 29.02,52.98 29.07,53 84.53,53 84.58,52.98 84.6,52.93 84.6,1.07 84.58,1.02 84.53,1 29.07,1 29.02,1.02 29,1.07 29,37 28.5,37 28.5,1.07 28.48,1.02 28.43,1 1.07,1 1.02,1.02 1,1.07 1,52.93 1.02,52.98 1.07,53 28.43,53 28.48,52.98 28.5,52.92 28.5,40.2 ; 23 cut-outs

Small or netless copper shapes (teardrops, artwork), in the pictures only: 4 on TOP, 3 on BOTTOM
